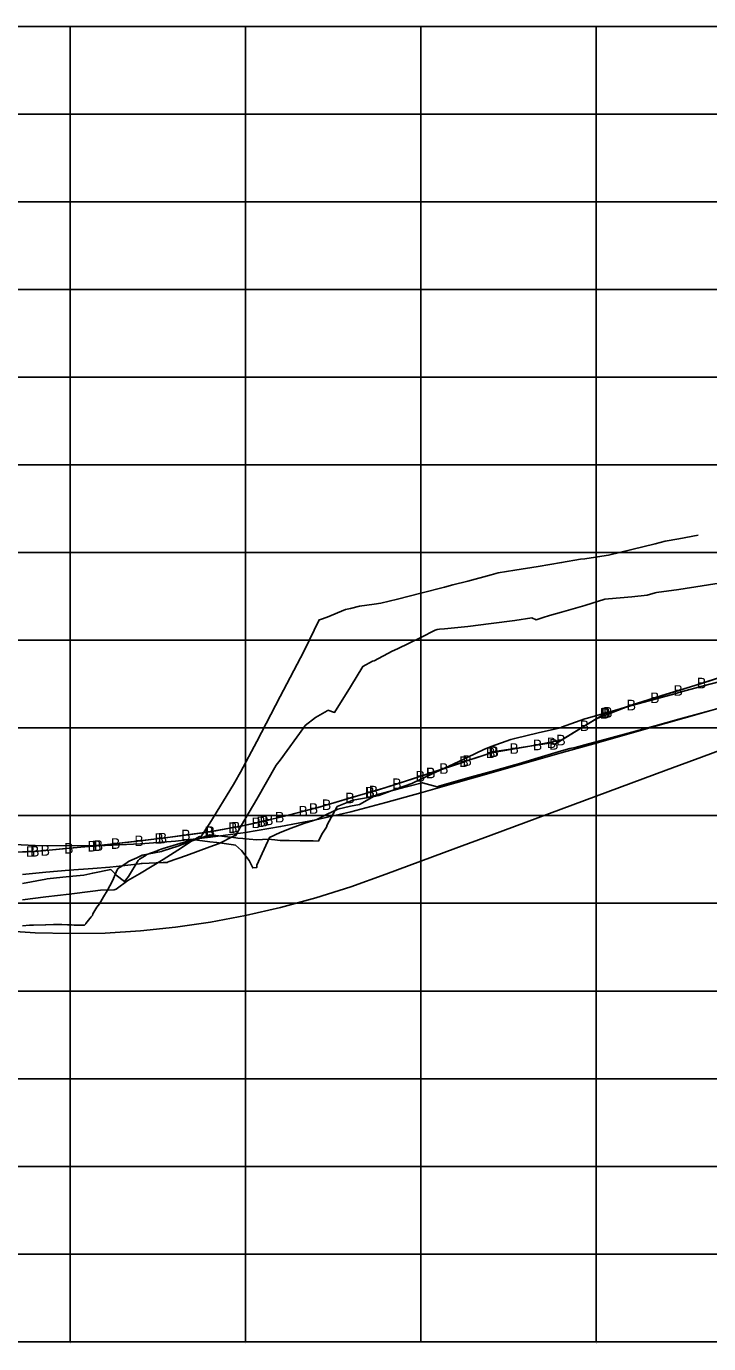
# Model space of a CAD drawing. Extents: x 76292 to 78417, y 50412 to 52585.
# Drawn here: x 76892.8 to 77087.4, y 50411.8 to 50787.3 of the extents above; entities that cross this region are included whole.
import ezdxf

# ---------------------------------------------------------------- set-up
doc = ezdxf.new("R2010")
doc.units = 0
for name, color, linetype in [('1', 7, 'Continuous'), ('2', 7, 'Continuous'), ('38', 7, 'Continuous'), ('5', 7, 'Continuous'), ('63', 7, 'Continuous')]:
    doc.layers.add(name, color=color, linetype=linetype)

msp = doc.modelspace()

# ---------------------------------------------------------------- linework, layer by layer
at = {"layer": '1'}
for p, q in [((76305.34, 50412.34), (78205.34, 50412.34)), ((76905.34, 50412.34), (76905.34, 50412.34)), ((76955.34, 50412.34), (76955.34, 50412.34)), ((77005.34, 50412.34), (77005.34, 50412.34)), ((77055.34, 50412.34), (77055.34, 50412.34))]:
    msp.add_line(p, q, dxfattribs=at)
for points in [[(76891.7, 50538.36), (76898.38, 50539.18), (76905.07, 50539.99), (76911.75, 50540.8), (76913.98, 50541.08), (76917.87, 50541.16), (76918.44, 50541.35), (76921.77, 50543.86), (76925.12, 50545.79), (76931.81, 50549.84), (76936.02, 50552.53), (76938.49, 50554.07), (76940.21, 50555.29), (76942.2, 50556.39), (76942.2, 50556.38), (76942.55, 50556.25), (76945.18, 50560.23), (76951.86, 50571.19), (76952.27, 50571.89), (76953.88, 50574.73), (76958.55, 50583.45), (76965.23, 50596.26), (76971.92, 50609.1), (76973.48, 50612.27), (76976.29, 50618.19), (76976.72, 50618.28), (76978.61, 50618.92), (76983.86, 50621.06), (76985.29, 50621.36), (76987.79, 50622.03), (76991.98, 50622.62), (76993.95, 50622.93), (76998.66, 50624.08), (77005.35, 50625.77), (77012.03, 50627.46), (77014.49, 50628.12), (77018.72, 50629.22), (77025.4, 50631.02), (77027.36, 50631.58), (77032.09, 50632.32), (77038.77, 50633.39), (77045.46, 50634.48), (77050.89, 50635.41), (77052.14, 50635.56), (77058.17, 50636.53), (77058.83, 50636.62), (77065.52, 50638.23), (77072.2, 50639.85), (77075.03, 50640.57), (77078.89, 50641.26), (77084.41, 50642.34)], [(76891.7, 50545.59), (76898.38, 50546.18), (76905.07, 50546.75), (76911.75, 50547.29), (76916.59, 50547.67), (76918.44, 50547.87), (76925.12, 50548.64), (76925.53, 50548.68), (76925.83, 50548.69), (76931.81, 50548.94), (76933.01, 50548.99), (76933.31, 50549.2), (76938.49, 50551.02), (76945.18, 50553.4), (76947.84, 50554.36), (76951.86, 50556.52), (76952.34, 50556.78), (76952.36, 50556.58), (76952.43, 50556.56), (76954.21, 50559.63), (76958.55, 50566.99), (76964.09, 50576.76), (76965.23, 50578.16), (76971.92, 50587.43), (76972.32, 50588), (76975.28, 50590.3), (76978.61, 50592.24), (76978.84, 50592.39), (76980.74, 50591.75), (76985.29, 50599.02), (76988.8, 50604.87), (76991.58, 50606.37), (76991.98, 50606.5), (76997.15, 50609.23), (76998.66, 50609.87), (77005.35, 50613.12), (77009.37, 50615.19), (77009.96, 50615.38), (77010.67, 50615.53), (77012.03, 50615.63), (77018.72, 50616.29), (77025.4, 50617.07), (77032.09, 50617.97), (77036.96, 50618.74), (77038.24, 50618.2), (77038.77, 50618.32), (77040.24, 50618.85), (77042.05, 50619.43), (77045.46, 50620.32), (77052.14, 50622.24), (77057.82, 50624.02), (77058.83, 50624.1), (77065.52, 50624.74), (77069.84, 50625.18), (77072.2, 50625.82), (77072.55, 50625.92), (77078.89, 50626.83), (77085.57, 50627.83), (77092.26, 50628.88)], [(76891.7, 50530.96), (76893.67, 50531.08), (76894.86, 50531.11), (76898.29, 50531.24), (76898.38, 50531.24), (76900.57, 50531.26), (76902.94, 50531.28), (76904.58, 50531.21), (76905.07, 50531.22), (76905.7, 50531.22), (76906.47, 50531.13), (76907.87, 50531.15), (76908.19, 50531.11), (76909.42, 50531.16), (76909.77, 50531.5), (76909.82, 50531.55), (76911.33, 50533.5), (76911.66, 50533.91), (76911.75, 50534.3), (76912.96, 50536.2), (76913.64, 50537.19), (76914.78, 50539.18), (76915.82, 50540.86), (76917.37, 50543.75), (76918.44, 50546.25), (76918.93, 50547.26), (76919.54, 50547.63), (76921.18, 50548.69), (76921.99, 50549.22), (76922.14, 50549.33), (76922.33, 50549.45), (76924.34, 50550.27), (76925.12, 50550.69), (76925.86, 50551.03), (76931.33, 50552.1), (76931.81, 50552.29), (76933.94, 50552.96), (76936.02, 50553.64), (76938.49, 50554.55), (76945.18, 50556.87), (76945.18, 50556.85), (76951.86, 50556.08), (76952.01, 50556.06), (76953.15, 50555.93), (76954.56, 50555.78), (76956.32, 50555.61), (76958.52, 50555.44), (76958.55, 50555.45), (76961.75, 50555.62), (76963.65, 50555.41), (76965.23, 50555.29), (76965.84, 50555.25), (76967.74, 50555.27), (76970.95, 50555.12), (76971.92, 50555.11), (76973.23, 50555.11), (76974.59, 50555.19), (76976.1, 50555.08), (76977.12, 50557.07), (76978.4, 50559.02), (76978.61, 50559.69), (76981.47, 50564.94), (76985.29, 50566.5), (76985.92, 50566.74), (76991.98, 50567.84), (76993.33, 50568.08), (76998.66, 50570.04), (77002.77, 50571.49), (77005.35, 50572.74), (77012.03, 50575.86), (77017.4, 50578.3), (77018.72, 50579.02), (77023.27, 50581.23), (77025.4, 50582.05), (77031.02, 50584.06), (77032.09, 50584.34), (77038.77, 50585.93), (77045.14, 50587.4), (77045.46, 50587.57), (77052.14, 50589.95), (77052.46, 50590.06), (77058.83, 50591.84), (77065.52, 50593.7), (77072.2, 50595.57), (77077.73, 50597.09), (77078.89, 50597.43), (77085.57, 50599.24), (77090.68, 50600.59)], [(76891.7, 50543.03), (76898.38, 50544.24), (76898.71, 50544.3), (76905.07, 50544.98), (76909.2, 50545.4), (76911.75, 50545.95), (76916.96, 50546.94), (76918.05, 50545.89), (76918.44, 50545.36), (76920.83, 50543.55), (76921.94, 50545.02), (76924.68, 50549.51), (76925.12, 50549.95), (76927.01, 50551.05), (76927.18, 50551.28), (76930.08, 50552.33), (76930.17, 50552.36), (76930.21, 50552.38), (76931.81, 50552.94), (76938.49, 50555), (76940.21, 50555.51), (76945.18, 50554.91), (76947.18, 50554.69), (76949.9, 50554.3), (76951.86, 50554.01), (76952.45, 50553.93), (76954.16, 50552.42), (76956.33, 50549.56), (76957.39, 50547.44), (76958.46, 50547.52), (76958.54, 50547.51), (76958.55, 50548.17), (76958.59, 50548.26), (76962.15, 50556.15), (76965.23, 50557.52), (76968.36, 50558.78), (76971.92, 50560.05), (76975.63, 50561.26), (76978.61, 50562.78), (76981.67, 50564.21), (76985.29, 50565.02), (76987.87, 50565.56), (76991.98, 50567.93), (76992.64, 50568.28), (76998.66, 50569.85), (77005.35, 50571.61), (77005.76, 50571.71), (77010.01, 50570.57), (77010.45, 50570.72), (77012.03, 50571.21), (77018.72, 50573.07), (77025.4, 50574.94), (77032.09, 50576.82), (77033.19, 50577.12), (77038.77, 50578.78), (77045.46, 50580.78), (77047.82, 50581.47), (77049.32, 50581.72), (77052.14, 50582.51), (77058.83, 50584.31), (77065.52, 50586.13), (77072.2, 50587.96), (77078.89, 50589.8), (77085.57, 50591.66), (77087.66, 50592.22)]]:
    msp.add_lwpolyline(points, dxfattribs=at)
at = {"layer": '2'}
msp.add_lwpolyline([(76891.7, 50552.01), (76894.14, 50552.12), (76895.37, 50552.17), (76895.37, 50552.17), (76895.37, 50552.17), (76895.37, 50552.17), (76895.37, 50552.17), (76895.38, 50552.17), (76898.38, 50552.43), (76905.07, 50553.02), (76911.75, 50553.61), (76913.04, 50553.72), (76913.53, 50553.8), (76918.44, 50554.37), (76925.12, 50555.14), (76930.83, 50555.8), (76931.81, 50555.93), (76938.49, 50556.83), (76945.11, 50557.73), (76945.18, 50557.74), (76945.44, 50557.78), (76951.86, 50558.91), (76952.7, 50559.06), (76958.55, 50560.3), (76959.92, 50560.59), (76960.81, 50560.78), (76960.82, 50560.78), (76960.82, 50560.78), (76962.11, 50561.11), (76965.23, 50561.91), (76971.92, 50563.61), (76974.85, 50564.36), (76974.89, 50564.37), (76978.61, 50565.44), (76985.29, 50567.37), (76990.9, 50569), (76990.92, 50569), (76990.92, 50569), (76990.96, 50569.01), (76991.01, 50569.03), (76991.98, 50569.34), (76998.66, 50571.44), (77005.35, 50573.56), (77008.3, 50574.49), (77008.34, 50574.51), (77012.03, 50575.76), (77017.79, 50577.71), (77018.72, 50578.02), (77025.4, 50580.25), (77026.17, 50580.5), (77026.25, 50580.53), (77026.39, 50580.58), (77032.09, 50581.46), (77038.77, 50582.49), (77042.73, 50583.09), (77043.43, 50582.65), (77045.46, 50583.88), (77052.14, 50587.97), (77057.89, 50591.47), (77057.96, 50591.51), (77058.03, 50591.53), (77058.22, 50591.59), (77058.83, 50591.78), (77065.52, 50593.86), (77072.2, 50595.94), (77078.89, 50598.03), (77085.57, 50600.13), (77090.54, 50601.69)], dxfattribs=at)
at = {"layer": '38'}
for points in [[(76885.34, 50551.75), (76895.34, 50552.16), (76905.34, 50553.04), (76915.34, 50554.01), (76925.34, 50555.16), (76935.34, 50556.41), (76945.34, 50557.76), (76955.34, 50559.62), (76965.34, 50561.94), (76975.34, 50564.5), (76985.34, 50567.39), (76995.34, 50570.4), (77005.34, 50573.56), (77015.34, 50576.88), (77025.34, 50580.22), (77035.34, 50581.96), (77045.34, 50583.81), (77055.34, 50589.92), (77065.34, 50593.8), (77075.34, 50596.92), (77085.34, 50600.05), (77095.34, 50603.23)], [(76885.34, 50551.75), (76895.34, 50552.16), (76905.34, 50553.04), (76915.34, 50554.01), (76925.34, 50555.16), (76935.34, 50556.41), (76945.34, 50557.76), (76955.34, 50559.62), (76965.34, 50561.94), (76975.34, 50564.5), (76985.34, 50567.39), (76995.34, 50570.4), (77005.34, 50573.56), (77015.34, 50576.88), (77025.34, 50580.22), (77035.34, 50581.96), (77045.34, 50583.81), (77055.34, 50589.92), (77065.34, 50593.8), (77075.34, 50596.92), (77085.34, 50600.05), (77095.34, 50603.23)], [(76885.34, 50554.27), (76895.34, 50553.83), (76905.34, 50553.69), (76915.34, 50553.85), (76925.34, 50554.32), (76935.34, 50555.09), (76945.34, 50556.16), (76955.34, 50557.53), (76965.34, 50559.2), (76975.34, 50561.18), (76985.34, 50563.46), (76995.34, 50566.04), (77005.34, 50568.85), (77015.34, 50571.69), (77025.34, 50574.53), (77035.34, 50577.36), (77045.34, 50580.2), (77055.34, 50583.04), (77065.34, 50585.87), (77075.34, 50588.71), (77085.34, 50591.54), (77095.34, 50594.38)], [(76885.34, 50529.64), (76895.34, 50528.96), (76905.34, 50528.71), (76915.34, 50528.88), (76925.34, 50529.49), (76935.34, 50530.52), (76945.34, 50531.98), (76955.34, 50533.86), (76965.34, 50536.17), (76975.34, 50538.91), (76985.34, 50542.08), (76995.34, 50545.67), (77005.34, 50549.37), (77015.34, 50553.07), (77025.34, 50556.77), (77035.34, 50560.47), (77045.34, 50564.18), (77055.34, 50567.88), (77065.34, 50571.58), (77075.34, 50575.28), (77085.34, 50578.99), (77095.34, 50582.69)]]:
    msp.add_lwpolyline(points, dxfattribs=at)
at = {"layer": '5'}
for p, q in [((77078.89, 50598.03), (77085.57, 50600.13)), ((77085.57, 50600.13), (77090.54, 50601.69)), ((77065.52, 50593.86), (77072.2, 50595.94)), ((77072.2, 50595.94), (77078.89, 50598.03)), ((77057.89, 50591.47), (77057.96, 50591.51)), ((77057.96, 50591.51), (77058.03, 50591.53)), ((77058.03, 50591.53), (77058.22, 50591.59)), ((77058.22, 50591.59), (77058.83, 50591.78)), ((77058.83, 50591.78), (77065.52, 50593.86)), ((77045.46, 50583.88), (77052.14, 50587.97)), ((77052.14, 50587.97), (77057.89, 50591.47)), ((77018.72, 50578.02), (77025.4, 50580.25)), ((77025.4, 50580.25), (77026.17, 50580.5)), ((77026.17, 50580.5), (77026.25, 50580.53)), ((77026.25, 50580.53), (77026.39, 50580.58)), ((77026.39, 50580.58), (77032.09, 50581.46)), ((77032.09, 50581.46), (77038.77, 50582.49)), ((77038.77, 50582.49), (77042.73, 50583.09)), ((77042.73, 50583.09), (77043.43, 50582.65)), ((77043.43, 50582.65), (77045.46, 50583.88)), ((77012.03, 50575.76), (77017.79, 50577.71)), ((77017.79, 50577.71), (77018.72, 50578.02)), ((76998.66, 50571.44), (77005.35, 50573.56)), ((77005.35, 50573.56), (77008.3, 50574.49)), ((77008.3, 50574.49), (77008.34, 50574.51)), ((77008.34, 50574.51), (77012.03, 50575.76)), ((76985.29, 50567.37), (76990.9, 50569)), ((76990.9, 50569), (76990.92, 50569)), ((76990.92, 50569), (76990.96, 50569.01)), ((76990.92, 50569), (76990.92, 50569)), ((76990.96, 50569.01), (76991.01, 50569.03)), ((76991.01, 50569.03), (76991.98, 50569.34)), ((76991.98, 50569.34), (76998.66, 50571.44)), ((76974.89, 50564.37), (76978.61, 50565.44)), ((76978.61, 50565.44), (76985.29, 50567.37)), ((76962.11, 50561.11), (76965.23, 50561.91)), ((76965.23, 50561.91), (76971.92, 50563.61)), ((76971.92, 50563.61), (76974.85, 50564.36)), ((76974.85, 50564.36), (76974.89, 50564.37)), ((76938.49, 50556.83), (76945.11, 50557.73)), ((76945.11, 50557.73), (76945.18, 50557.74)), ((76945.18, 50557.74), (76945.44, 50557.78)), ((76945.44, 50557.78), (76951.86, 50558.91)), ((76951.86, 50558.91), (76952.7, 50559.06)), ((76952.7, 50559.06), (76958.55, 50560.3)), ((76958.55, 50560.3), (76959.92, 50560.59)), ((76959.92, 50560.59), (76960.81, 50560.78)), ((76960.81, 50560.78), (76960.82, 50560.78)), ((76960.82, 50560.78), (76962.11, 50561.11)), ((76960.82, 50560.78), (76960.82, 50560.78)), ((76913.53, 50553.8), (76918.44, 50554.37)), ((76918.44, 50554.37), (76925.12, 50555.14)), ((76925.12, 50555.14), (76930.83, 50555.8)), ((76930.83, 50555.8), (76931.81, 50555.93)), ((76931.81, 50555.93), (76938.49, 50556.83)), ((76891.7, 50552.01), (76894.14, 50552.12)), ((76894.14, 50552.12), (76895.37, 50552.17)), ((76895.37, 50552.17), (76895.37, 50552.17)), ((76895.37, 50552.17), (76895.37, 50552.17)), ((76895.37, 50552.17), (76895.37, 50552.17)), ((76895.37, 50552.17), (76895.37, 50552.17)), ((76895.37, 50552.17), (76895.38, 50552.17)), ((76895.38, 50552.17), (76898.38, 50552.43)), ((76898.38, 50552.43), (76905.07, 50553.02)), ((76905.07, 50553.02), (76911.75, 50553.61)), ((76911.75, 50553.61), (76913.04, 50553.72)), ((76913.04, 50553.72), (76913.53, 50553.8))]:
    msp.add_line(p, q, dxfattribs=at)
at = {"layer": '63'}
for p, q in [((76305.34, 50787.34), (78205.34, 50787.34)), ((76305.34, 50787.34), (78205.34, 50787.34)), ((76905.34, 50412.34), (76905.34, 50787.34)), ((76955.34, 50412.34), (76955.34, 50787.34)), ((77005.34, 50412.34), (77005.34, 50787.34)), ((77055.34, 50412.34), (77055.34, 50787.34)), ((76305.34, 50762.34), (78205.34, 50762.34)), ((76305.34, 50737.34), (78205.34, 50737.34)), ((76305.34, 50712.34), (78205.34, 50712.34)), ((76305.34, 50687.34), (78205.34, 50687.34)), ((76305.34, 50662.34), (78205.34, 50662.34)), ((76305.34, 50637.34), (78205.34, 50637.34)), ((76305.34, 50612.34), (78205.34, 50612.34)), ((76305.34, 50587.34), (78205.34, 50587.34)), ((76305.34, 50562.34), (78205.34, 50562.34)), ((76305.34, 50537.34), (78205.34, 50537.34)), ((76305.34, 50512.34), (78205.34, 50512.34)), ((76305.34, 50487.34), (78205.34, 50487.34)), ((76305.34, 50462.34), (78205.34, 50462.34)), ((76305.34, 50437.34), (78205.34, 50437.34))]:
    msp.add_line(p, q, dxfattribs=at)

# ---------------------------------------------------------------- texts
at = {"layer": '1'}
for s, p in [('86', (76905.4, 50411.93)), ('+50', (76955.4, 50411.81)), ('87', (77005.4, 50411.94)), ('+50', (77055.4, 50411.81))]:
    msp.add_text(s, height=0.12, rotation=90, dxfattribs=at).set_placement(p)
at = {"layer": '5'}
for p in [(77077.39, 50596.53), (77084.07, 50598.63), (77064.02, 50592.36), (77070.7, 50594.44), (77056.39, 50589.97), (77056.46, 50590.01), (77056.53, 50590.03), (77056.72, 50590.09), (77057.33, 50590.28), (77050.64, 50586.47), (77037.27, 50580.99), (77041.23, 50581.59), (77041.93, 50581.15), (77043.96, 50582.38), (77023.9, 50578.75), (77024.67, 50579), (77024.75, 50579.03), (77024.89, 50579.08), (77030.59, 50579.96), (77010.53, 50574.26), (77016.29, 50576.21), (77017.22, 50576.52), (76997.16, 50569.94), (77003.85, 50572.06), (77006.8, 50572.99), (77006.84, 50573.01), (76989.4, 50567.5), (76989.42, 50567.5), (76989.42, 50567.5), (76989.46, 50567.51), (76989.51, 50567.53), (76990.48, 50567.84), (76973.35, 50562.86), (76973.39, 50562.87), (76977.11, 50563.94), (76983.79, 50565.87), (76957.05, 50558.8), (76958.42, 50559.09), (76959.31, 50559.28), (76959.32, 50559.28), (76959.32, 50559.28), (76960.61, 50559.61), (76963.73, 50560.41), (76970.42, 50562.11), (76936.99, 50555.33), (76943.61, 50556.23), (76943.68, 50556.24), (76943.94, 50556.28), (76950.36, 50557.41), (76951.2, 50557.56), (76896.88, 50550.93), (76903.57, 50551.52), (76910.25, 50552.11), (76911.54, 50552.22), (76912.03, 50552.3), (76916.94, 50552.87), (76923.62, 50553.64), (76929.33, 50554.3), (76930.31, 50554.43), (76892.64, 50550.62), (76893.87, 50550.67), (76893.87, 50550.67), (76893.87, 50550.67), (76893.87, 50550.67), (76893.87, 50550.67), (76893.88, 50550.67)]:
    msp.add_text('B', height=3, dxfattribs=at).set_placement(p)

doc.saveas('drawing.dxf')
